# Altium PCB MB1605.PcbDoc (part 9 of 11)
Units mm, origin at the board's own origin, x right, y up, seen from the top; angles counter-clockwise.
Board outline 100 x 79.6 mm, 6 copper layers (Top Layer, Signal Layer 1, Signal Layer 2, Signal Layer 3, Signal Layer 4, Bottom Layer), stack 1.549 mm thick; 644 components, 529 nets, 2853 pads, 1462 vias.
Unrouted connection lines stored in the file: 2.
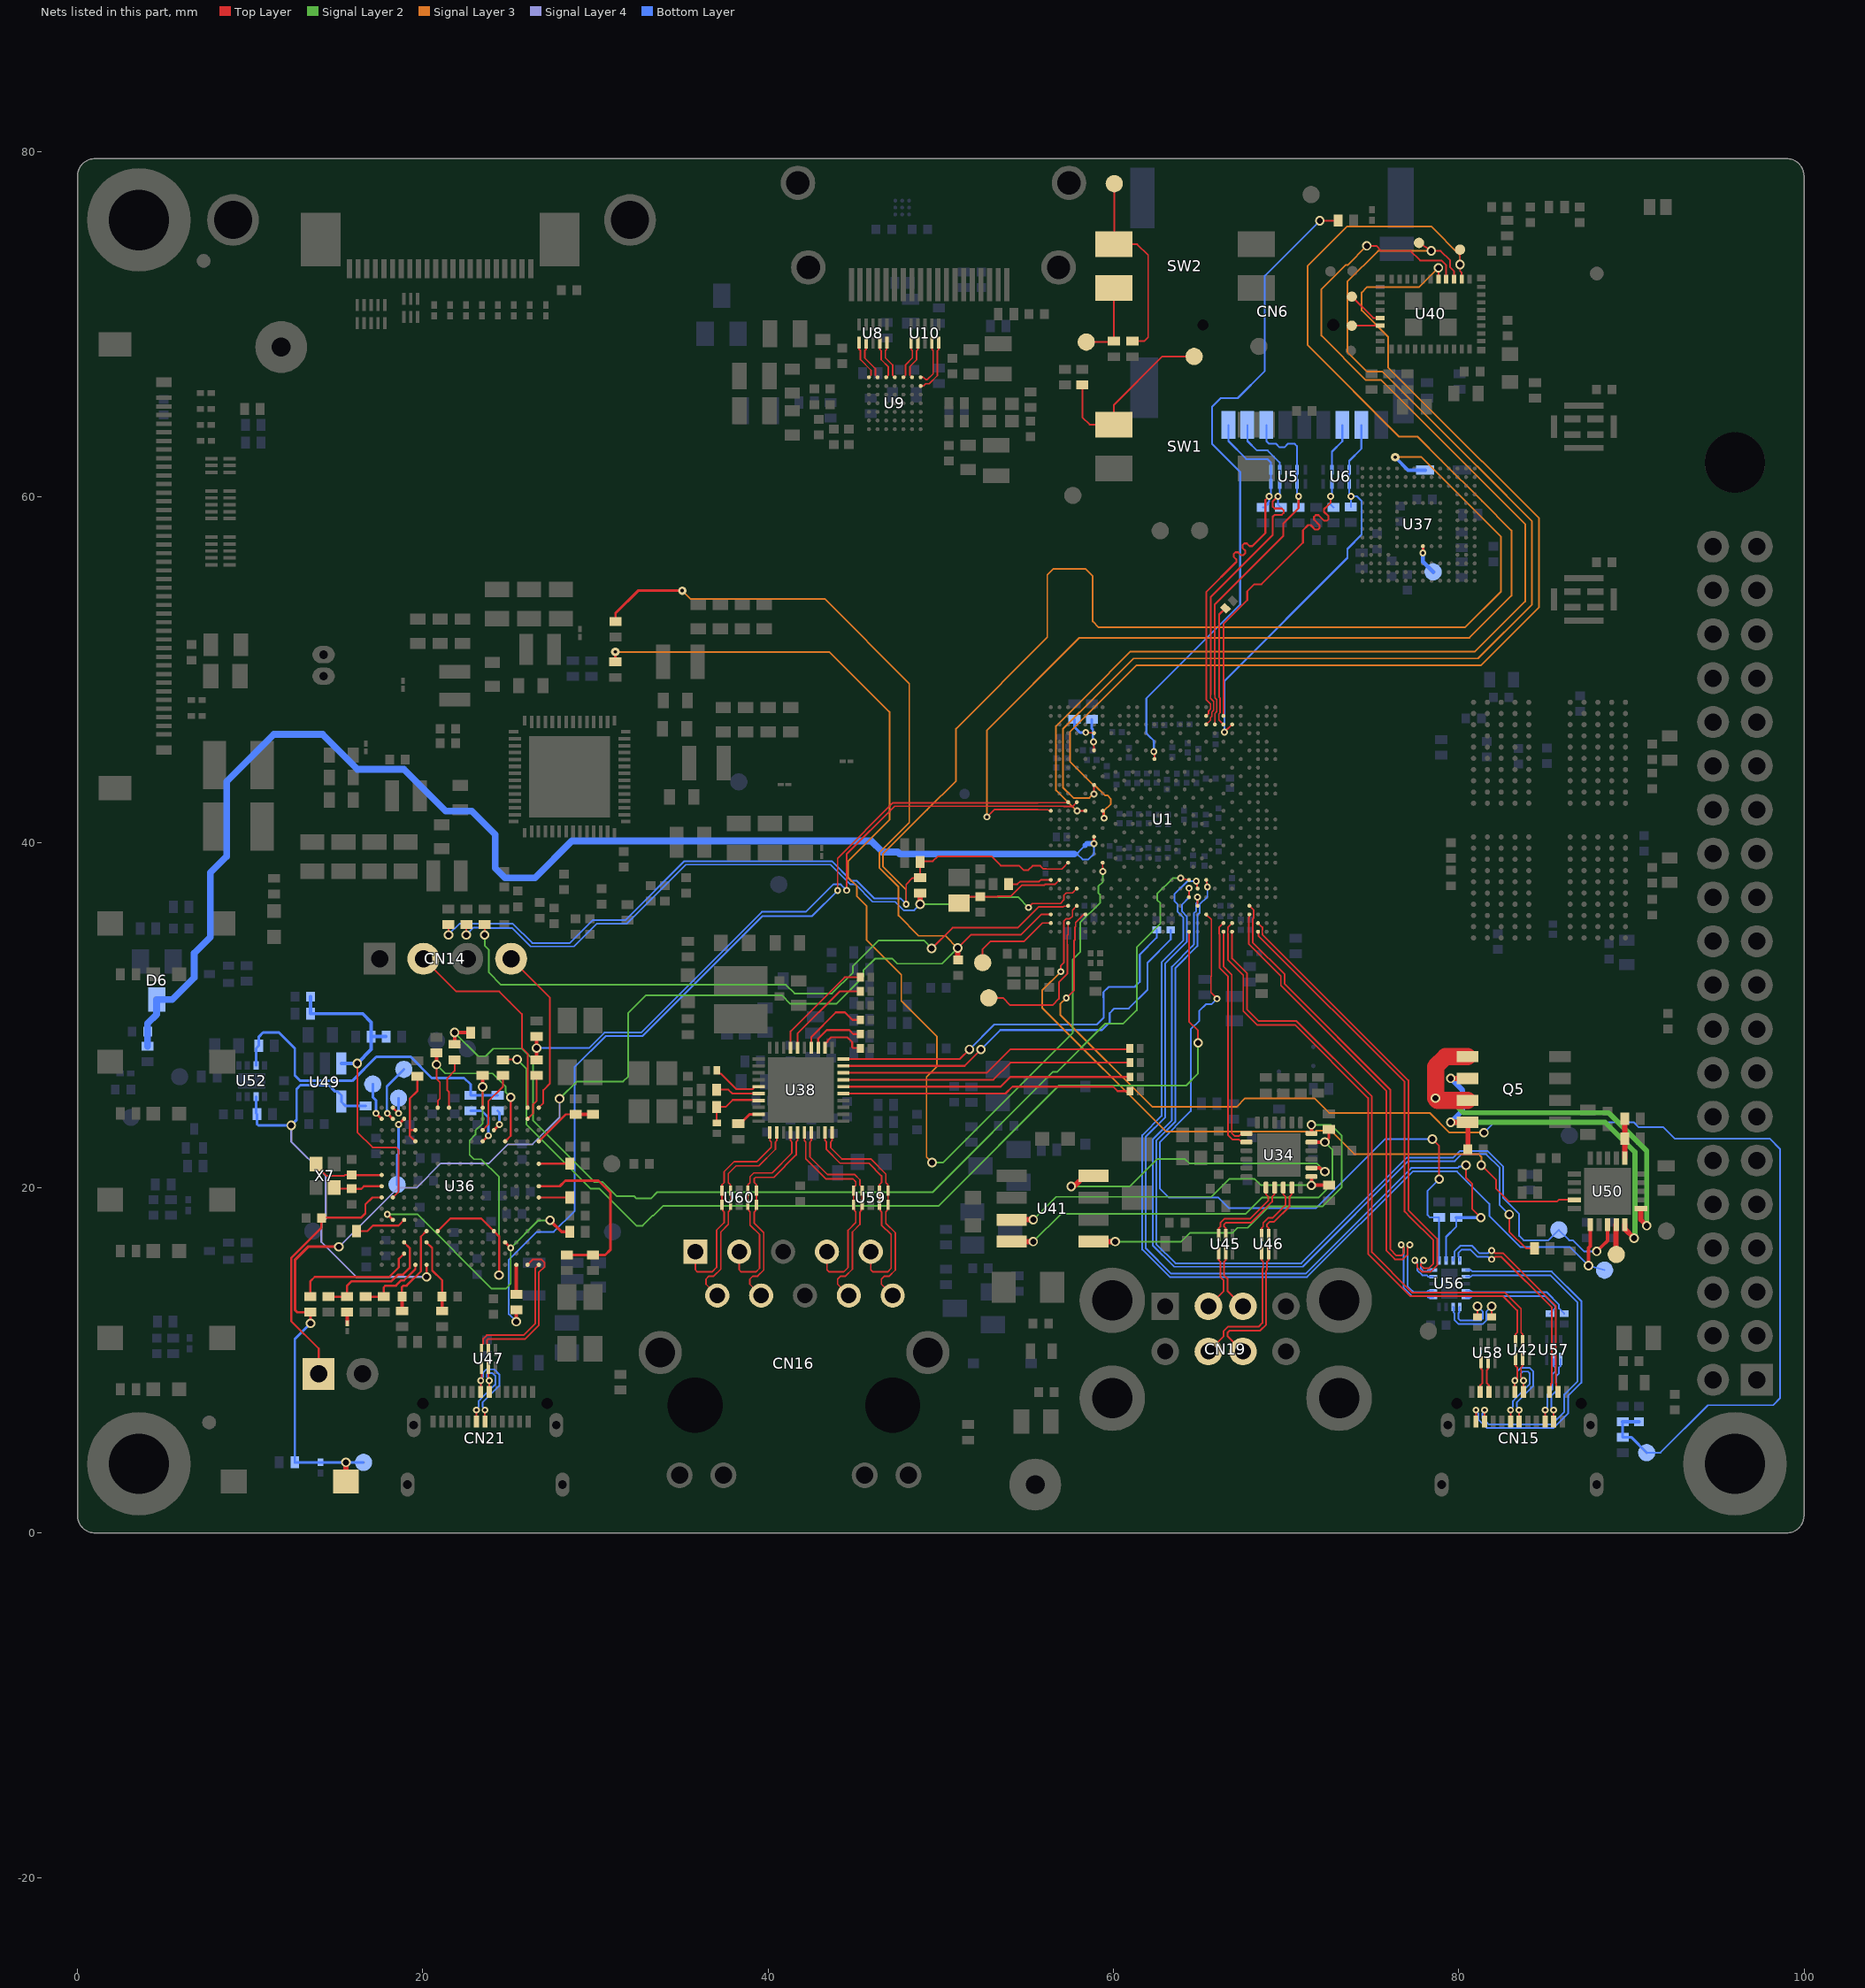
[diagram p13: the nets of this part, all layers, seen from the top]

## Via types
v1: diameter 0.55, hole 0.35, Top Layer to Bottom Layer, 823 vias
v2: diameter 0.4, hole 0.2, Top Layer to Bottom Layer, 235 vias
v3: diameter 0.4, hole 0.2, Top Layer to Bottom Layer, tented both sides, 216 vias
v4: diameter 0.5, hole 0.2, Top Layer to Bottom Layer, 159 vias
v5: diameter 0.25/0.3 (per signal layer), hole 0.1, Top Layer to Signal Layer 1, tented both sides, 29 vias

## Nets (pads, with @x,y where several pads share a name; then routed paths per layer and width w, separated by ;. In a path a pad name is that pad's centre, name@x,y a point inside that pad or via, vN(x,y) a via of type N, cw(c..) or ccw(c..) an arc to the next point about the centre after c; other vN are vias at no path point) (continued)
NetR121_2: R121.2 U38.24 | length 4.2
  Top Layer w0.11: U38.24@42.5,28.1 42.5,28.725 43.925,30.15 44.45,30.15 44.88,29.72 R121.2@45.345,29.72
NetR122_1: R122.1 SW1.3 TP24.1 | length 10.8
  Top Layer w0.1: R122.1@58.2,66.5 58.2,64.618 58.623,64.195 SW1.3@60.025,64.195 60.025,65.335 62.833,68.143 TP24.1@64.675,68.143
NetR123_1: R123.1 SW2.3 TP44.1 | length 11.5
  Top Layer w0.1: TP44.1@60.05,78.15 60.05,74.67 SW2.3@60.025,74.645 61.38,74.645 62.01,74.015 62.01,69.259 61.776,69.025 R123.1@61.1,69.025
NetR124_1: R124.1 SW2.4 TP31.1 | length 4.7
  Top Layer w0.1: TP31.1@58.425,68.975 59.975,68.975 R124.1@60.025,69.025 SW2.4@60.025,72.105
NetR147_2: R147.2 U38.23 | length 3.3
  Top Layer w0.11: U38.23@42.9,28.1 42.9,28.625 43.4,29.125 44.7,29.125 44.927,28.898 R147.2@45.345,28.898
NetR148_2: R148.2 U38.22 | length 2.9
  Top Layer w0.11: U38.22@43.3,28.1 43.3,28.35 43.345,28.395 43.381,28.395 43.445,28.459 43.445,28.514 43.636,28.705 44.147,28.705 44.595,28.705 44.868,28.432 44.868,28.146 44.933,28.082 45.327,28.082 R148.2@45.344,28.065
NetR149_2: R149.2 U38.27 | length 6.3
  Top Layer w0.11: U38.27@41.3,28.1 41.3,29.05 44.435,32.185 R149.2@45.345,32.185
NetR150_2: R150.2 U38.26 | length 5.5
  Top Layer w0.11: U38.26@41.7,28.1 41.7,28.925 44.14,31.365 R150.2@45.345,31.365
NetR155_2: R155.2 U36.B14 | length 2.7
  Top Layer w0.1: U36.B14@26.065,23.982 26.39,24.307 26.39,24.832 26.59,25.032 R155.2@26.59,26.507
NetR156_1: R156.1 U36.C4 U36.D4 | length 4.4
  Top Layer w0.12: U36.D4@19.565,22.682 19.24,23.007 19.24,23.332 ; U36.C4@19.565,23.332 19.24,23.332 ; R156.1@19.69,26.457 19.69,25.607 19.24,25.157 19.24,23.332
NetR161_2: R161.2 U38.20 | length 23.3
  Top Layer w0.11: U38.20@44.35,27.45 51.099,27.45 v1(51.656,28.007)
  Bottom Layer w0.11: v1(51.656,28.007) 53.099,29.449 59.037,29.449 59.434,29.846 59.434,31.012 59.426,31.02 59.426,31.326 59.723,31.623 61.229,31.623 61.525,31.919 61.525,33.498 62.506,34.479 R161.2@62.506,34.925
NetR164_2: R164.2 U38.19 | length 23.8
  Top Layer w0.11: U38.19@44.35,27.05 51.374,27.05 v1(52.322,27.998)
  Bottom Layer w0.11: v1(52.322,27.998) 53.449,29.125 59.331,29.125 59.784,29.578 59.784,30.104 60.055,30.375 60.888,30.375 61.981,31.469 61.981,33.039 63.319,34.377 R164.2@63.319,34.925
NetR167_2: R167.2 U38.18 | length 17.2
  Top Layer w0.11: U38.18@44.35,26.65 46.627,26.65 52.666,26.65 54.023,28.007 60.887,28.007 R167.2@60.945,28.065
NetR173_2: R173.2 U38.17 | length 17
  Top Layer w0.11: U38.17@44.35,26.25 53.044,26.25 54.034,27.24 R173.2@60.96,27.24
NetR176_2: R176.2 U38.35 | length 3
  Top Layer w0.11: R176.2@37.025,26.8 37.025,26.75 37.17,26.605 37.256,26.605 38.156,25.705 39.091,25.705 39.155,25.769 39.155,25.805 39.2,25.85 U38.35@39.45,25.85
NetR178_2: R178.2 U38.16 | length 16.8
  Top Layer w0.11: U38.16@44.35,25.85 53.462,25.85 54.027,26.415 R178.2@60.96,26.415
NetR181_1: R181.1 U36.F15 | length 1.8
  Top Layer w0.12: U36.F15@26.715,21.382 R181.1@28.515,21.382
NetR182_2: R182.2 U38.36 | length 2.5
  Top Layer w0.11: R182.2@37.025,25.675 37.7,25.675 37.925,25.45 U38.36@39.45,25.45
NetR185_2: R185.2 U38.15 | length 16.9
  Top Layer w0.11: U38.15@44.35,25.45 53.752,25.45 54.149,25.847 59.983,25.847 60.24,25.59 R185.2@60.96,25.59
NetR188_2: R188.2 R196.2 U38.37 | length 4.5
  Top Layer w0.11: U38.37@39.45,25.05 39.45,25.08 37.955,25.08 37.55,24.675 R188.2@37.025,24.675 ; R188.2@37.025,24.675 R196.2@37.025,23.75 R188.2@37.025,24.675
NetR194_1: R194.1 U36.J15 | length 1.8
  Top Layer w0.12: U36.J15@26.715,19.432 R194.1@28.515,19.432
NetR199_1: R199.1 U38.39 | length 1.4
  Top Layer w0.15: R199.1@38.275,23.7 38.37,23.7 38.92,24.25 U38.39@39.45,24.25
NetR211_2: R211.2 U36.R13 | length 1.7
  Top Layer w0.2: R211.2@25.415,13.812 U36.R13@25.415,15.532
NetR212_1: R212.1 U36.P3 | length 7.3
  Top Layer w0.12: R212.1@13.49,13.682 13.49,14.582 13.74,14.832 18.05,14.832 18.615,15.397 18.615,15.882 U36.P3@18.915,16.182
NetR231_1: R231.1 R232.2 U50.11 | length 2.3
  Top Layer w0.3: U50.11@89.613,21.723 89.613,22.848 R232.2@89.613,24.003
NetR240_1: R240.1 R241.1 R242.1 U52.7 | length 19.6
  Bottom Layer w0.15: U52.7@10.336,27.077 10.336,28.067 R242.1@10.486,28.217 10.486,28.723 10.745,28.982 11.665,28.982 12.586,28.061 12.586,26.503 12.904,26.186 15.912,26.186 17.302,27.575 19.3,27.575 20.521,26.354 22.393,26.354 22.765,25.982 R241.1@22.765,25.35 R240.1@24.335,25.35
NetR250_1: R250.1 U1.D6 | length 1.7
  Top Layer w0.1: v3(58.396,46.369) U1.D6@58.875,46.325
  Bottom Layer w0.15: R250.1@57.744,47.12 57.744,46.681 58.055,46.369 v3(58.396,46.369)
NetR251_1: R251.1 U1.F6 | length 1.8
  Top Layer w0.1: v3(58.85,45.825) U1.F6@58.875,45.325
  Bottom Layer w0.15: R251.1@58.751,47.12 58.751,46.59 58.81,46.531 58.81,45.865 v3(58.85,45.825)
NetTP12_1: TP12.1 U1.AF1 | length 5.4
  Top Layer w0.09: 55.625,35.07 55.645,35.09 55.652,35.09 55.887,35.325 U1.AF1@56.375,35.325
  Top Layer w0.1: TP12.1@52.427,33.031 52.427,33.809 52.875,34.258 54.813,34.258 55.625,35.07
NetTP14_1: TP14.1 U40.18 | length 1.6
  Top Layer w0.1: TP14.1@73.81,69.925 U40.18@75.45,69.925
NetTP20_1: TP20.1 U40.17 | length 2.2
  Top Layer w0.1: TP20.1@73.81,71.607 75.042,70.375 U40.17@75.45,70.375
NetTP21_1: TP21.1 U37.H5 | length 1.7
  Top Layer w0.15: v2(77.925,56.755) U37.H5@77.925,57.155
  Bottom Layer w0.25: v2(77.925,56.755) 77.925,56.256 TP21.1@78.516,55.665
NetTP26_1: TP26.1 U36.B2 | length 3.4
  Top Layer w0.15: v3(17.94,24.307) U36.B2@18.265,23.982
  Bottom Layer w0.15: v3(17.94,24.307) 17.915,24.332 17.915,25.865 TP26.1@18.9,26.85
NetTP27_1: TP27.1 U36.B3 | length 4
  Top Layer w0.15: v3(18.59,23.657) U36.B3@18.915,23.982
  Bottom Layer w0.15: TP27.1@18.505,20.182 18.505,21.877 18.59,21.962 v3(18.59,23.657)
NetTP28_1: TP28.1 U36.B1 | length 2.2
  Top Layer w0.15: v3(17.29,24.307) U36.B1@17.615,23.982
  Bottom Layer w0.15: TP28.1@17.098,26 17.098,25.25 17.29,25.057 v3(17.29,24.307)
NetTP29_1: TP29.1 U36.A2 | length 1.3
  Top Layer w0.15: U36.A2@18.265,24.632 v3(18.59,24.307)
  Bottom Layer w0.15: v3(18.59,24.307) TP29.1@18.59,25.182
NetTP38_1: TP38.1 U50.4 | length 1.7
  Top Layer w0.3: TP38.1@89.113,16.144 U50.4@89.113,17.873
NJTRST: TP42.1 U1.AF3 | length 9
  Top Layer w0.09: 57.325,34.075 57.325,34.605 57.375,34.655 U1.AF3@57.375,35.325
  Top Layer w0.1: TP42.1@52.78,30.993 53.598,30.993 54.023,30.568 56.469,30.568 56.837,30.936 56.837,31.895 57.325,32.383 57.325,34.075
NRST: B1.1 C33.2 R33.1 R81.1 R212.2 TP22.1 U1.AE1 U15.1 | length 113.5
  Top Layer w0.09: 55.625,35.636 55.814,35.825 U1.AE1@56.375,35.825
  Top Layer w0.1: C33.2@50.975,33.225 C33.2@51,33.2 ; v1(50.975,33.875) 51.758,34.658 54.647,34.658 55.625,35.636
  Top Layer w0.15: v1(13.49,12.137) R212.2@13.49,12.782 12.723,12.782 12.609,12.896 12.609,15.828 13.356,16.575 v1(15.137,16.575) ; R81.1@31.163,52.798 31.163,53.273 32.465,54.575 v4(35.025,54.575)
  Top Layer w0.3: B1.1@15.549,2.979 v1(15.549,4.09) ; C33.2@50.975,33.225 v1(50.975,33.875)
  Signal Layer 2 w0.1: v1(27.92,25.15) 28.92,26.15 31.601,26.15 31.9,26.449 31.9,30.121 32.924,31.145 40.789,31.145 41.284,30.65 43.949,30.65 45.514,32.216 45.514,32.586 46.19,33.261 47.201,33.261 47.49,32.972 50.072,32.972 v1(50.975,33.875)
  Signal Layer 3 w0.1: v4(35.025,54.575) 35.502,54.098 43.277,54.098 48.175,49.2 48.175,41.14 46.442,39.407 46.442,38.529 47.554,37.417 47.554,35.752 48.721,34.586 50.264,34.586 v1(50.975,33.875)
  Signal Layer 4 w0.1: v1(15.137,16.575) 18.553,19.991 19.629,19.991 21.045,21.407 23.829,21.407 24.929,22.507 26.353,22.507 27.92,24.074 v1(27.92,25.15)
  Bottom Layer w0.15: v1(13.49,12.137) 12.586,11.233 R33.1@12.586,4.09 U15.1@14.062,4.09 v1(15.549,4.09) TP22.1@16.565,4.09
NRSTC1MS: D7.2 R27.1 R59.1 R272.1 U1.W3 | length 110.3
  Top Layer w0.09: 56.11,38.46 57.01,38.46 U1.W3@57.375,38.825
  Top Layer w0.1: R59.1@21.48,35.245 21.488,35.237 v1(21.488,34.633) ; v2(47.997,36.42) 47.997,37.566 48.363,37.932 48.782,37.932 R272.1@48.805,37.955 R27.1@48.805,38.872 48.805,38.904 49.542,38.904 49.831,39.194 49.936,39.194 49.938,39.192 50.559,39.192 50.561,39.194 52.93,39.194 53.474,38.65 54.531,38.65 54.787,38.394 55.077,38.394 55.319,38.635 55.764,38.635 55.939,38.46 56.11,38.46
  Signal Layer 3 w0.1: v2(47.997,36.42) 47.997,37.257 46.642,38.611 46.642,39.324 49.196,41.878 49.204,41.878 50.883,43.557 50.883,46.589 56.169,51.875 56.169,55.485 56.534,55.85 58.361,55.85 58.797,55.414 58.797,52.793 59.141,52.45 80.367,52.45 82.45,54.533 82.45,57.701 77.84,62.311 v4(76.32,62.311)
  Bottom Layer w0.1: v1(21.488,34.633) 21.488,34.653 22.123,35.288 25.217,35.288 26.335,34.17 28.515,34.17 29.833,35.488 31.724,35.488 35.146,38.91 43.695,38.91 44.83,37.775 45.122,37.775 46.138,36.759 47.658,36.759 v2(47.997,36.42)
  Bottom Layer w0.2: v4(76.32,62.311) 77.068,61.563 D7.2@78.055,61.563
OSC32_IN: C86.1 U1.AA2 X1.2 | length 6.4
  Top Layer w0.09: 55.625,37.525 56,37.525 56.05,37.575 56.625,37.575 U1.AA2@56.875,37.825
  Top Layer w0.1: X1.2@51.059,36.475 51.434,36.85 53.271,36.85 53.296,36.875 54.052,36.875 54.702,37.525 55.625,37.525
OSC32_OUT: R64.1 U1.AA1 | length 2.5
  Top Layer w0.09: 56.05,37.825 U1.AA1@56.375,37.825
  Top Layer w0.1: R64.1@53.935,37.575 54.436,37.575 54.597,37.735 55.695,37.735 55.784,37.825 56.05,37.825
PMIC_WAKEUPn: R46.1 U1.W7 | length 69.4
  Top Layer w0.09: U1.W7@59.375,38.825 v3(59.387,38.317)
  Top Layer w0.15: R46.1@31.15,50.448 v4(31.15,51.033)
  Signal Layer 2 w0.1: v1(49.5,21.45) 50.111,21.45 57.646,28.985 57.646,33.218 58.075,33.647 58.075,35.343 59.225,36.493 59.225,36.97 59.119,37.076 59.119,37.455 59.387,37.722 v3(59.387,38.317)
  Signal Layer 3 w0.1: v4(31.15,51.033) 43.548,51.033 47.028,47.553 47.028,41.303 44.625,38.9 44.625,37.98 45.132,37.473 45.132,36.893 45.698,36.327 45.698,34.356 47.715,32.34 47.715,30.826 49.774,28.767 49.774,27.012 49.175,26.413 49.175,21.775 v1(49.5,21.45)
PWR_CPU_ON: R60.1 R272.2 U1.AB4 | length 41.5
  Top Layer w0.09: 55.625,36.455 56.215,36.455 56.22,36.46 56.93,36.46 57.125,36.655 57.125,36.929 57.271,37.075 57.625,37.075 U1.AB4@57.875,37.325
  Top Layer w0.095: 55.57,36.455 55.625,36.455
  Top Layer w0.1: v1(22.514,34.64) 22.514,35.229 R60.1@22.53,35.245 ; v2(55.077,36.225) 55.307,36.455 55.57,36.455
  Top Layer w0.3: v1@48.805,36.419 R272.2@48.805,37.055
  Signal Layer 2 w0.1: v1(48.806,36.417) 51.182,36.417 51.598,36.834 54.469,36.834 v2(55.077,36.225)
  Bottom Layer w0.1: v1(22.514,34.64) 22.944,35.07 23.756,35.07 23.781,35.045 25.177,35.045 26.252,33.97 28.742,33.97 30.06,35.288 31.807,35.288 35.229,38.71 43.612,38.71 44.747,37.575 45.039,37.575 46.055,36.559 47.363,36.559 47.852,36.07 48.459,36.07 v1(48.806,36.417)
PWR_ON: R61.1 U1.AD3 | length 39.6
  Top Layer w0.09: 56.084,36.26 57.09,36.26 57.128,36.298 57.348,36.298 U1.AD3@57.375,36.325
  Top Layer w0.1: v1(23.58,34.64) R61.1@23.58,35.245 ; v1(49.475,33.855) 50.678,35.058 54.455,35.058 55.657,36.26 56.084,36.26
  Signal Layer 2 w0.1: v1(23.58,34.64) 23.58,34.015 23.824,33.771 23.824,32.458 24.537,31.745 41.037,31.745 41.532,31.25 43.7,31.25 44.914,32.464 44.914,32.834 46.397,34.317 49.013,34.317 v1(49.475,33.855)
RJ452_D1_N: CN16.2 U38.2 U60.4 U60.7 | length 12.5
  Top Layer w0.09: CN16.2@37.055,13.75 36.4,14.405 36.4,14.695 36.577,14.872 36.856,14.872 37.26,15.276 37.26,17.432 37.7,17.872 37.7,18.597 37.77,18.667 37.77,18.957 U60.7@37.825,19.012 U60.4@37.825,19.832 37.825,20.167 37.7,20.292 37.7,20.815 38.145,21.26 39.46,21.26 40.425,22.225 40.425,22.65 40.5,22.725 U38.2@40.5,23.2
RJ452_D1_P: CN16.1 U38.1 U60.5 U60.6 | length 12.5
  Top Layer w0.09: CN16.1@35.785,16.29 35.785,15.245 35.908,15.122 36.752,15.122 37.01,15.38 37.01,17.536 37.45,17.976 37.45,18.597 37.38,18.667 37.38,18.957 U60.6@37.325,19.012 U60.5@37.325,19.832 37.325,20.167 37.45,20.292 37.45,20.919 38.041,21.51 39.356,21.51 40.175,22.329 40.175,22.65 40.1,22.725 U38.1@40.1,23.2
RJ452_D2_N: CN16.4 U38.5 U60.1 U60.10 | length 12.2
  Top Layer w0.09: CN16.4@39.595,13.75 38.94,14.405 38.94,14.695 39.117,14.872 39.396,14.872 39.75,15.226 39.75,17.389 39.2,17.939 39.2,18.597 39.27,18.667 39.27,18.957 U60.10@39.325,19.012 U60.1@39.325,19.832 39.325,20.167 39.2,20.292 39.2,20.529 39.27,20.599 40.329,20.599 41.625,21.895 41.625,22.65 41.7,22.725 U38.5@41.7,23.2
RJ452_D2_P: CN16.3 U38.4 U60.2 U60.9 | length 12.2
  Top Layer w0.09: CN16.3@38.325,16.29 38.325,15.245 38.448,15.122 39.292,15.122 39.5,15.33 39.5,17.285 38.95,17.835 38.95,18.597 38.88,18.667 38.88,18.957 U60.9@38.825,19.012 U60.2@38.825,19.832 38.825,20.167 38.95,20.292 38.95,20.632 39.166,20.849 40.225,20.849 41.375,21.999 41.375,22.65 41.3,22.725 U38.4@41.3,23.2
RJ452_D3_N: CN16.8 U38.7 U59.4 U59.7 | length 12.7
  Top Layer w0.09: U38.7@42.5,23.2 42.5,22.725 42.425,22.65 42.425,21.779 43.445,20.759 45.014,20.759 45.32,20.452 45.32,20.13 45.373,20.077 45.39,20.077 45.445,20.022 U59.7@45.445,19.012 45.39,18.957 45.39,18.667 45.32,18.597 45.32,17.872 44.88,17.432 44.88,15.276 44.476,14.872 44.197,14.872 44.02,14.695 44.02,14.405 CN16.8@44.675,13.75
RJ452_D3_P: CN16.7 U38.6 U59.5 U59.6 | length 12.7
  Top Layer w0.09: U38.6@42.1,23.2 42.1,22.725 42.175,22.65 42.175,21.675 43.341,20.509 44.91,20.509 45.07,20.349 45.07,20.13 45.017,20.077 45,20.077 44.945,20.022 U59.6@44.945,19.012 45,18.957 45,18.667 45.07,18.597 45.07,17.976 44.63,17.536 44.63,15.38 44.372,15.122 43.528,15.122 43.405,15.245 CN16.7@43.405,16.29
RJ452_D4_N: CN16.10 U38.10 U59.1 U59.10 | length 12.9
  Top Layer w0.09: U38.10@43.7,23.2 43.7,22.725 43.625,22.65 43.625,22.307 44.269,21.663 45.942,21.663 46.82,20.785 46.82,20.292 46.945,20.167 U59.1@46.945,19.832 U59.10@46.945,19.012 46.89,18.957 46.89,18.667 46.82,18.597 46.82,17.939 47.37,17.389 47.37,15.226 47.016,14.872 46.737,14.872 46.56,14.695 46.56,14.405 CN16.10@47.215,13.75
RJ452_D4_P: CN16.9 U38.9 U59.2 U59.9 | length 12.9
  Top Layer w0.09: U38.9@43.3,23.2 43.3,22.725 43.375,22.65 43.375,22.204 44.165,21.413 45.838,21.413 46.57,20.681 46.57,20.292 46.445,20.167 U59.2@46.445,19.832 U59.9@46.445,19.012 46.5,18.957 46.5,18.667 46.57,18.597 46.57,17.835 47.12,17.285 47.12,15.33 46.912,15.122 46.068,15.122 45.945,15.245 CN16.9@45.945,16.29
RX1_N: CN15.B10 U56.11 | length 20.2
  Top Layer w0.1: CN15.B10@81.5,6.46 v2(81.5,7.12)
  Bottom Layer w0.1: U56.11@80.408,14.836 80.698,14.836 80.788,14.926 85.299,14.926 86.882,13.343 86.882,8.793 86.111,8.023 86.111,7.01 85.392,6.291 84.25,6.291 81.726,6.291 81.629,6.388 81.36,6.657 81.36,6.911 81.5,7.051 v2(81.5,7.12)
RX1_P: CN15.B11 U56.10 | length 21.3
  Top Layer w0.1: CN15.B11@81,6.46 v2(81,7.12)
  Bottom Layer w0.1: U56.10@80.408,15.236 80.698,15.236 80.788,15.146 85.39,15.146 87.102,13.434 87.102,8.702 86.331,7.931 86.331,6.919 85.483,6.071 81.634,6.071 81.14,6.565 81.14,6.911 81,7.051 v2(81,7.12)
RX2_N: CN15.A10 U56.9 | length 12.4
  Top Layer w0.1: v2(81.9,15.852) 81.969,15.852 82.109,15.992 82.471,15.992 85.396,13.067 85.396,13.005 85.396,10.581 85.396,8.684 85.35,8.638 85.35,8.26 CN15.A10@85.25,8.16
  Bottom Layer w0.1: U56.9@80.068,15.776 80.068,15.916 79.978,16.006 79.978,16.214 80.18,16.416 80.67,16.416 81.094,15.992 81.691,15.992 81.831,15.852 v2(81.9,15.852)
RX2_P: CN15.A11 U56.8 | length 13.2
  Top Layer w0.1: v2(81.9,16.352) 81.969,16.352 82.109,16.212 82.562,16.212 85.616,13.158 85.616,8.689 85.65,8.655 85.65,8.26 CN15.A11@85.75,8.16
  Bottom Layer w0.1: U56.8@79.668,15.776 79.668,15.916 79.758,16.006 79.758,16.305 80.089,16.636 80.761,16.636 81.185,16.212 81.691,16.212 81.831,16.352 v2(81.9,16.352)
SD.SDMMC1_CK: R9.1 U1.C21 | length 7
  Top Layer w0.09: 66.115,47.085 66.115,47.434 66.175,47.494 66.175,48.356 66.125,48.406 66.125,48.575 66.125,48.615
  Top Layer w0.11: 66.115,47.085 U1.C21@66.375,46.825 ; 66.125,48.615 66.125,53.197 R9.1@66.49,53.562
SD.SDMMC1_CMD: CN6.3 R37.1 U1.C20 U5.4 U5.7 | length 21.9
  Top Layer w0.09: U1.C20@65.875,46.825 65.875,47.462 65.985,47.572 65.985,48.267 65.875,48.377 65.875,48.575
  Top Layer w0.11: 65.875,48.575 65.875,53.79 69.841,57.756 69.841,58.466 70.725,59.35 v2(70.725,60.042)
  Bottom Layer w0.11: CN6.3@68.86,64.175 68.86,63.24 69.013,63.087 69.417,63.087 69.626,62.877 69.897,62.877 70.106,63.087 70.491,63.087 70.625,62.952 U5.4@70.625,61.582 U5.7@70.625,60.762 70.625,60.142 v2(70.725,60.042) R37.1@70.725,59.393
SD.SDMMC1_D0: CN6.7 R38.1 U1.B21 U6.2 U6.9 | length 22.7
  Top Layer w0.11: U1.B21@66.375,47.325 66.375,52.65 67.75,54.025 67.75,54.538 68.162,54.95 68.57,54.95 70.976,57.356 70.976,58.076 71.272,58.372 71.426,58.372 71.686,58.112 71.841,58.112 71.944,58.215 71.944,58.369 71.617,58.696 71.617,58.85 71.72,58.953 71.875,58.953 72.201,58.627 72.356,58.627 72.459,58.73 72.459,58.884 72.199,59.144 72.199,59.299 72.406,59.506 72.577,59.677 v2(72.577,60.042)
  Bottom Layer w0.11: R38.1@72.75,59.393 72.577,59.566 v2(72.577,60.042) 72.654,60.12 U6.9@72.654,60.762 U6.2@72.654,61.582 72.654,62.629 73.26,63.235 CN6.7@73.26,64.175
SD.SDMMC1_D1: CN6.8 R39.1 U1.C22 U6.4 U6.7 | length 23.1
  Top Layer w0.11: v3(66.43,46.389) U1.C22@66.875,46.825
  Bottom Layer w0.11: v3(66.43,46.389) 66.43,49.352 73.554,56.476 73.554,56.996 74.375,57.816 74.375,59.775 74.108,60.042 v2(73.754,60.042) ; R39.1@73.754,59.43 v2(73.754,60.042) ; CN6.8@74.36,64.175 74.36,62.8 73.654,62.094 U6.4@73.654,61.582 U6.7@73.654,60.762 73.654,60.142 v2(73.754,60.042)
SD.SDMMC1_D2: CN6.1 R35.1 U1.B19 U5.1 U5.10 | length 22.4
  Top Layer w0.09: U1.B19@65.375,47.325 65.515,47.465 65.515,47.611 65.625,47.721 65.625,48.015 65.375,48.265
  Top Layer w0.11: 65.375,48.265 65.375,54.493 67.076,56.194 67.115,56.233 67.115,56.388 66.961,56.541 66.961,56.695 67.064,56.798 67.218,56.798 67.377,56.639 67.532,56.639 67.635,56.742 67.635,56.897 67.476,57.056 67.476,57.21 67.579,57.313 67.733,57.313 67.887,57.16 68.041,57.16 68.179,57.298 68.8,57.918 68.8,59.761 68.8,59.826 v2(69.016,60.042)
  Bottom Layer w0.11: CN6.1@66.66,64.175 66.66,63.24 67.698,62.202 68.919,62.202 69.125,61.996 U5.1@69.125,61.582 U5.10@69.125,60.762 69.125,60.151 v2(69.016,60.042) v2(69.016,60.042) 69.015,59.747 68.956,59.688 68.956,59.593 68.756,59.393 R35.1@68.661,59.393
SD.SDMMC1_D3: CN6.2 R36.1 U1.C19 U5.2 U5.9 | length 22.1
  Top Layer w0.09: U1.C19@65.375,46.825 65.625,47.075 65.625,47.229 65.695,47.299 65.695,47.537 65.805,47.647 65.805,48.166 65.63,48.342 65.63,48.575
  Top Layer w0.11: 65.63,48.575 65.63,54.198 69.225,57.793 69.225,58.443 69.225,58.862 69.334,58.972 69.752,58.972 69.861,59.081 69.861,59.226 69.752,59.336 69.334,59.336 69.225,59.445 69.225,59.742 69.504,60.021 v2(69.525,60.042)
  Bottom Layer w0.11: CN6.2@67.76,64.175 67.76,63.247 68.308,62.698 68.929,62.698 69.625,62.002 U5.2@69.625,61.582 U5.9@69.625,60.762 69.625,60.142 v2(69.525,60.042) 69.525,59.568 R36.1@69.7,59.393
SD.uSD_DETECT: R40.1 U1.G13 | length 38.6
  Top Layer w0.1: U1.G13@62.375,44.825 v3@62.375,45.3
  Top Layer w0.11: v1(71.95,76) 72.99,76 R40.1@73.015,76.025
  Bottom Layer w0.11: v3@62.343,45.253 62.343,45.88 62.045,46.178 61.906,46.317 61.906,48.34 67.341,53.775 67.341,61.453 65.707,63.087 65.707,65.218 66.215,65.726 67.197,65.726 68.768,67.297 68.768,72.818 v1(71.95,76)
  other v3: 62.34,45.25
SRC_GDPG: C94.1 Q5.2 Q5.4 R325.2 U50.5 | length 24.1
  Top Layer w0.2: Q5.2@80.528,26.329 Q5.2@80.533,26.334
  Top Layer w0.3: v1(79.533,23.789) Q5.4@80.528,23.789 ; v1(79.533,26.329) Q5.2@80.528,26.329 ; C94.1@80.533,22.224 Q5.4@80.533,23.794 ; U50.5@89.613,17.873 89.613,17.623 v1(90.163,17.073)
  Signal Layer 2 w0.3: v1(79.533,23.789) 88.476,23.789 90.2,22.065 90.2,17.11 v1(90.163,17.073)
  Bottom Layer w0.3: v1(79.533,23.789) 80.225,24.481 R325.2@80.225,25.178 80.225,25.637 v1(79.533,26.329)
SRC_GDPS: Q5.1 Q5.3 R325.1 U50.6 | length 25.5
  Top Layer w0.3: U50.6@90.538,18.798 90.538,18.148 v1(90.888,17.798)
  Top Layer w1: Q5.3@80.52,25.052 78.781,25.052 v1(78.655,25.178) 78.655,27.006 79.241,27.592 Q5.1@80.52,27.592
  Signal Layer 2 w0.3: v1(78.655,25.178) 79.433,25.178 80.273,24.338 88.683,24.338 90.888,22.133 v1(90.888,17.798)
  Bottom Layer w0.3: v1(78.655,25.178) R325.1@79.325,25.178
STLK_LED: R130.1 R131.2 U36.D15 | length 3.8
  Top Layer w0.12: U36.D15@26.715,22.682 28.283,24.25 R130.1@28.83,24.25
  Top Layer w0.2: R130.1@28.83,24.25 R131.2@29.858,24.25
STLK_NRST: C149.2 JP3.1 U36.J1 | length 14.7
  Top Layer w0.12: JP3.1@13.965,9.211 13.965,10.68 12.374,12.271 12.374,15.925 14.131,17.683 C149.2@14.131,18.239 ; C149.2@14.126,18.257 16.42,18.257 16.675,18.512 16.675,19.032 17.075,19.432 U36.J1@17.615,19.432
STLK_OSC_IN: C133.2 U36.G1 X7.1 | length 4.1
  Top Layer w0.1: X7.1@13.815,21.357 13.815,21.307 14.44,20.682 15.44,20.682 15.49,20.732 C133.2@15.885,20.732
  Top Layer w0.12: C133.2@15.885,20.732 U36.G1@17.615,20.732
STLK_OSC_OUT: C140.1 U36.H1 X7.3 | length 2.8
  Top Layer w0.1: X7.3@14.865,20.007 14.94,19.932 C140.1@15.885,19.932
  Top Layer w0.12: C140.1@15.885,19.932 16.44,19.932 16.59,20.082 U36.H1@17.615,20.082
STLK_SWCLK: CN14.2 U36.A14 | length 12.6
  Top Layer w0.1: CN14.2@20.035,33.257 21.93,31.363 24.431,31.363 25.045,30.748 25.74,30.053 25.74,28.092 26.065,27.767 U36.A14@26.065,24.632
STLK_SWDIO: CN14.4 U36.A15 | length 9.8
  Top Layer w0.1: CN14.4@25.115,33.257 27.365,31.007 27.365,26.04 26.975,25.65 26.975,24.892 U36.A15@26.715,24.632
STLK_UCPD_CC1_C: C157.1 R217.1 U36.M5 | length 5.3
  Top Layer w0.12: 19.058,14.325 19.89,15.157 19.89,17.157 U36.M5@20.215,17.482
  Top Layer w0.125: C157.1@18.795,13.682 18.795,14.251 18.868,14.325 19.058,14.325
  Top Layer w0.2: R217.1@18.795,12.857 C157.1@18.795,13.682
STLK_UCPD_CC2_C: C158.1 R218.1 U36.N5 | length 4.3
  Top Layer w0.12: U36.N5@20.215,16.832 20.54,16.507 20.54,15.207 21.115,14.632 C158.1@21.115,13.682
  Top Layer w0.2: R218.1@21.115,12.857 C158.1@21.115,13.682
STLK_USB_CN_N: CN21.A7 CN21.B7 U47.2 | length 5.5
  Top Layer w0.1: CN21.B7@23.1,6.46 v2(23.1,7.12) ; U47.2@23.8,9.561 23.8,8.87 v2(23.85,8.82) CN21.A7@23.85,8.16
  Bottom Layer w0.1: v2(23.1,7.12) 23.1,7.189 23.24,7.329 23.24,7.642 23.324,7.726 23.961,8.364 24.205,8.607 24.205,9.089 24.039,9.255 23.769,9.255 23.71,9.196 23.71,9.029 23.85,8.889 v2(23.85,8.82)
STLK_USB_CN_P: CN21.A6 CN21.B6 U47.1 | length 6.3
  Top Layer w0.1: CN21.A6@23.35,8.16 v2(23.35,8.82) 23.4,8.87 U47.1@23.4,9.561 ; CN21.B6@23.6,6.46 v2(23.6,7.12)
  Bottom Layer w0.1: v2(23.35,8.82) 23.35,8.889 23.49,9.029 23.49,9.288 23.677,9.475 24.13,9.475 24.425,9.18 24.425,8.516 23.46,7.551 23.46,7.329 23.6,7.189 v2(23.6,7.12)
STLK_USB_N: U36.R14 U47.5 | length 8.9
  Top Layer w0.1: U47.5@23.8,10.611 23.8,10.861 23.71,10.951 23.71,11.154 23.788,11.232 25.93,11.232 26.725,12.027 26.725,15.1 27.05,15.425 27.05,15.65 26.85,15.85 26.383,15.85 U36.R14@26.065,15.532
STLK_USB_P: U36.R15 U47.6 | length 7.5
  Top Layer w0.1: U47.6@23.4,10.611 23.4,10.861 23.49,10.951 23.49,11.245 23.697,11.452 25.839,11.452 26.505,12.118 26.505,15.322 U36.R15@26.715,15.532
STLK_VCP_RX: R154.1 U36.C10 | length 3.7
  Top Layer w0.1: U36.C10@23.465,23.332 23.79,23.657 23.79,24.994 24.64,25.844 R154.1@24.64,26.507
STLK_VCP_TX: R134.1 U36.A7 | length 3
  Top Layer w0.1: U36.A7@21.515,24.632 21.515,25.531 21.415,25.631 21.415,26.337 21.84,26.762 R134.1@21.84,27.407
T_JTDI: R207.1 U36.L3 | length 3
  Top Layer w0.12: R207.1@16.165,17.482 16.79,17.482 17.115,17.807 18.59,17.807 U36.L3@18.915,18.132
T_PWR_EN: R229.2 R239.2 U36.R5 U49.4 U52.2 | length 26
  Top Layer w0.12: v1(20.215,14.832) U36.R5@20.215,15.532
  Signal Layer 4 w0.12: v1(12.374,23.612) 12.374,22.673 14.374,20.673 14.374,18.214 14.126,17.966 14.126,16.853 16.147,14.832 v1(20.215,14.832)
  Bottom Layer w0.15: U52.2@10.336,25.277 10.336,24.307 R239.2@10.386,24.257 10.386,23.7 10.474,23.612 v1(12.374,23.612) 12.688,23.926 12.688,25.713 12.905,25.931 14.553,25.931 14.916,25.568 15.056,25.568 15.281,25.343 U49.4@15.281,24.993 15.281,24.969 15.506,24.744 R229.2@16.69,24.744
T_PWR_EXT: R215.1 R216.1 U36.R4 | length 4.1
  Top Layer w0.12: R215.1@16.69,13.682 R216.1@17.74,13.682 17.74,14.232 17.833,14.325 18.445,14.325 18.752,14.632 18.915,14.632 19.565,15.282 U36.R4@19.565,15.532
T_PWR_INT: C25.2 R226.2 R227.2 R230.2 U36.J2 U49.3 | length 18.9
  Top Layer w0.1: v1(16.202,27.193) 16.202,23.213 17.086,22.329 18.454,22.329 18.59,22.193 18.59,19.757 U36.J2@18.265,19.432
  Bottom Layer w0.2: C25.2@13.492,31.068 R230.2@13.492,30.075 16.52,30.075 17.015,29.58 R226.2@17.015,28.75 ; U49.3@15.281,27.193 v1(16.202,27.193) 17.015,28.005 R226.2@17.015,28.75 ; R227.2@17.865,28.75 R226.2@17.015,28.75
T_PWR_LED: R132.2 R133.2 U36.H15 | length 10.5
  Top Layer w0.15: U36.H15@26.715,20.082 27.935,20.082 28.26,20.407 30.181,20.407 30.858,19.73 30.858,16.389 30.563,16.094 R132.2@29.85,16.094 R133.2@28.35,16.094
T_PWR_SEL1: R241.2 U36.D10 | length 2.7
  Top Layer w0.15: U36.D10@23.465,22.682 v3(23.79,23.007)
  Bottom Layer w0.15: R241.2@22.765,24.45 23.41,24.45 23.79,24.07 v3(23.79,23.007)
T_PWR_SEL2: R240.2 U36.C11 | length 1.3
  Top Layer w0.15: U36.C11@24.115,23.332 v3(24.44,23.657)
  Bottom Layer w0.15: R240.2@24.335,24.45 24.44,24.345 v3(24.44,23.657)
T_SWCLK: R153.1 U36.A10 U36.M6 U36.M11 | length 20.6
  Top Layer w0.12: U36.M6@20.865,17.482 21.603,18.22 23.377,18.22 U36.M11@24.115,17.482 24.415,17.182 v1(24.415,14.932) ; U36.A10@23.465,24.632 v1(23.465,25.832)
  Top Layer w0.2: v1(23.465,25.832) R153.1@23.465,26.507
  Signal Layer 2 w0.1: v1(23.465,25.832) 23.465,23.715 23.05,23.3 23.05,23.072 22.705,22.727 22.705,21.902 22.96,21.647 23.378,21.647 24.415,20.61 v1(24.415,14.932)
T_SWDIO: R209.1 U36.L2 U36.N12 | length 16.4
  Top Layer w0.15: v3(17.94,18.457) U36.L2@18.265,18.132 ; U36.N12@24.765,16.832 v3(25.09,16.507)
  Top Layer w0.2: v1(27.37,18.107) 28.034,17.443 R209.1@28.515,17.443
  Signal Layer 2 w0.1: v3(17.94,18.457) 19.69,18.457 23.997,14.15 24.8,14.15 25.09,14.44 v3(25.09,16.507) 26.69,18.107 v1(27.37,18.107)
T_SWO: R129.1 U36.A6 U36.D12 | length 11.3
  Top Layer w0.1: v1(20.79,27.132) 20.79,26.303 20.99,26.103 20.99,25.157 20.865,25.032 U36.A6@20.865,24.632
  Top Layer w0.12: U36.D12@24.765,22.682 25.09,23.007 v1(25.09,25.232)
  Top Layer w0.2: v1(20.79,27.132) R129.1@20.79,27.807
  Signal Layer 2 w0.1: v1(20.79,27.132) 21.304,26.618 24.029,26.618 24.785,25.862 24.785,25.537 v1(25.09,25.232)
T_VCC: LNK13.2 R214.2 | length 0.6
  Top Layer w0.2: LNK13.2@15.615,12.137 R214.2@15.615,12.782
T_VCC_AIN: R213.1 R214.1 U36.N3 | length 7.4
  Top Layer w0.12: R213.1@14.54,13.682 R214.1@15.615,13.682 15.615,14.325 15.873,14.582 18.177,14.582 18.561,14.966 18.856,14.966 19.24,15.35 19.24,16.507 U36.N3@18.915,16.832
TCPP_EN: R10.1 U1.AD18 | length 51.2
  Top Layer w0.1: U1.AD18@64.875,36.325 v3(64.875,36.829) ; v1(82.926,18.448) 82.926,17.455 83.896,16.485 R10.1@84.4,16.485
  Bottom Layer w0.1: v3(64.875,36.829) 64.866,36.82 64.866,36.543 64.798,36.474 64.798,36.026 64.658,35.887 64.658,34.075 64.579,33.995 64.579,33.992 63.387,32.8 63.387,23.901 62.28,22.793 62.28,16.654 63.514,15.42 70.966,15.42 77.087,21.54 79.771,21.54 80.161,21.93 81.588,21.93 82.37,21.148 82.37,19.984 82.368,19.981 82.368,19.006 v1(82.926,18.448)
TCPP_INTN: U1.AD4 U50.19 | length 43
  Top Layer w0.09: 57.125,34.075 57.125,35.429 57.271,35.575 57.479,35.575 57.625,35.721 57.625,36.075 U1.AD4@57.875,36.325
  Top Layer w0.1: v2(56.956,32.51) 56.956,32.865 57.125,33.033 57.125,34.075 ; v1(81.307,21.305) 82.17,20.443 82.17,19.94 82.9,19.21 85.712,19.21 85.799,19.298 U50.19@86.688,19.298
  Signal Layer 3 w0.1: v2(56.956,32.51) 55.868,31.421 55.868,30.421 63.051,23.238 71.27,23.238 71.294,23.215 71.646,23.215 71.723,23.292 72.609,23.292 73.95,21.951 81.142,21.951 81.307,21.786 v1(81.307,21.305)
TMDS_CLK_N: U9.B7 U10.10 | length 3.2
  Top Layer w0.09: U9.B7@48.836,66.435 48.996,66.435 49.121,66.56 49.329,66.56 49.804,67.035 49.804,68.478 49.879,68.553 U10.10@49.879,68.948
TMDS_CLK_P: U9.A7 U10.9 | length 2.7
  Top Layer w0.09: U9.A7@48.836,66.935 48.996,66.935 49.121,66.81 49.226,66.81 49.554,67.139 49.554,67.211 49.554,68.15 49.554,68.478 49.479,68.553 U10.9@49.479,68.948
TMDS_D0_N: U9.A6 U10.7 | length 2.3
  Top Layer w0.09: U9.A6@48.336,66.935 48.211,67.06 48.211,67.567 48.604,67.96 48.604,68.478 48.679,68.553 U10.7@48.679,68.948
TMDS_D0_P: U9.A5 U10.6 | length 2.3
  Top Layer w0.09: U9.A5@47.836,66.935 47.961,67.06 47.961,67.67 48.354,68.063 48.354,68.478 48.279,68.553 U10.6@48.279,68.948
TMDS_D1_N: U8.10 U9.A4 | length 2.3
  Top Layer w0.09: U8.10@46.872,68.948 46.872,68.553 46.797,68.478 46.797,68.063 47.211,67.649 47.211,67.06 U9.A4@47.336,66.935
TMDS_D1_P: U8.9 U9.A3 | length 2.3
  Top Layer w0.09: U8.9@46.472,68.948 46.472,68.553 46.547,68.478 46.547,67.96 46.961,67.546 46.961,67.06 U9.A3@46.836,66.935
TMDS_D2_N: U8.7 U9.A2 | length 2.4
  Top Layer w0.09: U8.7@45.672,68.948 45.672,68.553 45.597,68.478 45.597,68.063 46.211,67.448 46.211,67.06 U9.A2@46.336,66.935
TMDS_D2_P: U8.6 U9.A1 | length 2.4
  Top Layer w0.09: U8.6@45.272,68.948 45.272,68.553 45.347,68.478 45.347,67.959 45.961,67.345 45.961,67.06 U9.A1@45.836,66.935
TX1_N: CN15.A3 U58.2 | length 1.8
  Top Layer w0.1: U58.2@81.7,9.888 81.7,9.493 81.625,9.418 81.625,9.144 81.625,8.68 81.75,8.555 CN15.A3@81.75,8.16
TX1_P: CN15.A2 U58.1 | length 1.8
  Top Layer w0.1: CN15.A2@81.25,8.16 81.25,8.555 81.375,8.68 81.375,9.144 81.375,9.419 81.3,9.493 U58.1@81.3,9.888
TX2_N: CN15.B3 U57.2 | length 3.9
  Top Layer w0.1: CN15.B3@85,6.46 v2(85,7.12)
  Bottom Layer w0.1: v2(85,7.12) 85.14,7.26 85.14,8.032 85.429,8.32 85.429,9.187 85.588,9.346 85.588,9.583 85.498,9.673 U57.2@85.498,10.073
TX2_P: CN15.B2 U57.1 | length 3.9
  Top Layer w0.1: CN15.B2@85.5,6.46 v2(85.5,7.12)
  Bottom Layer w0.1: v2(85.5,7.12) 85.36,7.26 85.36,7.941 85.649,8.229 85.649,9.096 85.808,9.255 85.808,9.583 85.898,9.673 U57.1@85.898,10.073
TX10_N: C265.1 U56.16 | length 4.4
  Top Layer w0.1: C265.1@81.906,12.516 v1(81.906,13.13)
  Bottom Layer w0.1: U56.16@79.668,13.096 79.699,13.065 79.699,12.775 79.758,12.716 79.758,12.331 79.992,12.096 81.383,12.096 81.606,12.32 81.606,12.831 v1(81.906,13.13)
TX10_P: C100.1 U56.15 | length 3.7
  Top Layer w0.1: C100.1@81.087,12.516 v1(81.087,13.13)
  Bottom Layer w0.1: U56.15@80.068,13.096 80.037,13.065 80.037,12.775 79.978,12.716 79.978,12.422 80.084,12.316 80.175,12.316 81.158,12.316 81.291,12.316 81.386,12.411 81.386,12.831 v1(81.087,13.13)
TX20_N: C267.1 U56.14 | length 6
  Bottom Layer w0.1: U56.14@80.408,13.636 80.698,13.636 80.788,13.726 82.375,13.726 83.7,13.726 84.995,13.726 85.592,13.13 85.592,13.001 C267.1@85.292,12.701
TX20_P: C266.1 U56.13 | length 6.4
  Bottom Layer w0.1: U56.13@80.408,14.036 80.698,14.036 80.788,13.946 85.087,13.946 85.812,13.221 85.812,13.001 C266.1@86.111,12.701
UART5_RX: R125.1 R155.1 U1.M4 | length 40.1
  Top Layer w0.09: 55.625,42.094 57.123,42.094 57.141,42.075 57.625,42.075 57.87,42.32 U1.M4@57.875,42.32
  Top Layer w0.093: 55.56,42.094 55.625,42.094
  Top Layer w0.1: v2(44.55,37.221) 44.55,39.322 47.321,42.094 55.56,42.094
  Top Layer w0.2: R155.1@26.59,27.407 v1(26.59,28.082) R125.1@26.59,28.757
  Bottom Layer w0.1: v1(26.59,28.082) 29.612,28.082 30.512,28.982 32.644,28.982 39.638,35.976 42.189,35.976 43.773,37.56 44.211,37.56 v2(44.55,37.221)
UART5_TX: R211.1 U1.M3 | length 53.8
  Top Layer w0.09: 55.625,42.294 57.252,42.294 57.257,42.298 57.348,42.298 U1.M3@57.375,42.325
  Top Layer w0.1: v2(44.025,37.21) 44.025,39.08 47.239,42.294 55.625,42.294
  Top Layer w0.2: v1(25.415,12.237) R211.1@25.415,12.912
  Bottom Layer w0.1: v1(25.415,12.237) 24.977,12.675 24.977,15.819 26.59,17.432 27.585,17.432 28.785,18.632 28.785,26.972 30.595,28.782 32.727,28.782 39.67,35.725 42.54,35.725 v2(44.025,37.21)
UCPD_CC1: TP37.1 U1.AB18 U50.1 | length 58.9
  Top Layer w0.1: v3(64.8,37.75) U1.AB18@64.875,37.325
  Top Layer w0.2: v1(87.515,15.488) 87.515,16.507 87.613,16.604 U50.1@87.613,17.873
  Bottom Layer w0.1: v3(64.8,37.75) 64.28,37.75 63.529,36.999 63.529,36.614 63.714,36.43 63.714,35.984 64.058,35.64 64.058,34.32 63.813,34.075 62.787,33.049 62.787,24.149 61.67,23.032 61.67,16.415 63.266,14.82 71.214,14.82 77.335,20.94 79.898,20.94 81.77,19.068 81.77,18.371 83.591,16.55 86.453,16.55 v1(87.515,15.488) TP37.1@88.449,15.218
UCPD_CC2: TP36.1 U1.AA19 U50.3 | length 57.5
  Top Layer w0.1: U1.AA19@65.375,37.825 v3(65.444,37.416)
  Top Layer w0.2: v1(87.99,16.31) 88.303,16.622 88.309,16.622 88.588,16.901 88.588,16.907 88.613,16.932 U50.3@88.613,17.873
  Bottom Layer w0.1: v3(65.444,37.416) 65.444,36.852 64.988,36.395 64.988,35.909 64.858,35.78 64.858,34.075 64.858,33.989 63.587,32.717 63.587,23.818 62.48,22.711 62.48,16.737 63.597,15.62 70.883,15.62 77.004,21.74 79.689,21.74 80.078,22.13 81.671,22.13 82.57,21.231 82.57,19.901 82.568,19.899 82.568,19.407 83.5,18.475 83.5,17.207 83.757,16.95 85.198,16.95 TP36.1@85.798,17.551 86.399,16.95 86.618,16.95 87.258,16.31 v1(87.99,16.31)
USART1_CTS: U1.N7 U40.5 | length 65
  Top Layer w0.1: U1.N7@59.375,41.825 59.437,41.504 v3(59.457,41.4) ; U40.5@78.825,72.625 v1(78.825,73.275)
  Signal Layer 3 w0.1: v3(59.457,41.4) 59.457,41.826 59.855,42.224 59.855,42.514 59.644,42.725 59.505,42.725 58.975,43.255 58.9,43.255 57.479,44.676 57.479,46.408 59.646,48.575 61.321,50.25 81.278,50.25 84.65,53.622 84.65,58.764 81.346,62.068 81.306,62.109 75.919,67.496 75.919,69.265 74.375,70.809 74.375,71.851 74.674,72.15 77.7,72.15 v1(78.825,73.275)
USART1_RTS: U1.N5 U40.4 | length 69.1
  Top Layer w0.09: v3(57.9,41.825) U1.N5@58.375,41.825
  Top Layer w0.1: v1(74.675,74.55) 75.225,74.55 75.5,74.275 77.191,74.275 77.766,73.7 79.001,73.7 79.275,73.426 U40.4@79.275,72.625
  Signal Layer 3 w0.1: v3(57.9,41.825) 57.863,41.825 56.679,43.009 56.679,46.739 58.515,48.575 60.99,51.05 80.947,51.05 83.85,53.953 83.85,58.433 81.346,60.937 80.174,62.109 75.508,66.775 74.613,66.775 72.045,69.343 72.045,72.041 73.443,73.44 73.565,73.44 v1(74.675,74.55)
USART1_RX: TP9.1 U1.K6 U40.3 | length 68.8
  Top Layer w0.09: v3(58.875,42.8) U1.K6@58.875,43.325
  Top Layer w0.1: TP9.1@77.7,74.725 v1(78.406,74.258) 78.957,74.258 79.506,73.708 79.506,73.306 79.725,73.087 U40.3@79.725,72.625
  Signal Layer 3 w0.1: v3(58.875,42.8) 58.84,42.8 58.61,42.57 57.686,42.57 57.079,43.178 57.079,46.573 59.08,48.575 61.155,50.65 81.113,50.65 84.25,53.787 84.25,58.599 81.346,61.502 80.74,62.109 75.574,67.275 74.679,67.275 73.55,68.404 73.55,72.475 75.333,74.258 v1(78.406,74.258)
USART1_TX: TP1.1 U1.N1 U40.2 | length 79.9
  Top Layer w0.09: 55.625,41.894 56.207,41.894 56.251,41.85 56.35,41.85 U1.N1@56.375,41.825
  Top Layer w0.1: v2(52.675,41.475) 53.094,41.894 55.625,41.894 ; TP1.1@80.075,74.331 v1(80.075,73.473) 80.075,73.1 80.175,73 U40.2@80.175,72.625
  Signal Layer 3 w0.1: v2(52.675,41.475) 52.675,46.498 58.027,51.85 80.616,51.85 83.05,54.284 83.05,58.059 81.346,59.763 79.001,62.109 77.609,63.5 76.55,63.5 71.245,68.805 71.245,73.371 73.549,75.675 78.4,75.675 80.075,74 v1(80.075,73.473)
USART2_RX: R107.1 R134.2 U1.AA17 | length 61.7
  Top Layer w0.1: v3(63.9,37.925) 63.94,37.885 64.055,37.885 U1.AA17@64.375,37.825
  Top Layer w0.2: R134.2@21.84,28.307 v1(21.84,28.982) R107.1@22.775,28.982
  Signal Layer 2 w0.1: v1(21.84,28.982) 23.206,27.616 23.641,27.616 24.077,28.052 25.736,28.052 26.387,27.401 26.387,23.879 29.929,20.337 30.398,20.337 31.235,19.5 32.251,19.5 32.376,19.375 33.212,19.375 33.575,19.737 49.53,19.737 56.505,26.712 56.751,26.712 59.539,29.5 60.576,29.5 61.35,30.274 61.35,33.93 62.725,35.305 62.725,36.47 62.525,36.67 62.525,37.007 63.443,37.925 v3(63.9,37.925)
USART2_TX: R154.2 U1.AG17 | length 58.2
  Top Layer w0.09: 64.375,34.075 U1.AG17@64.375,34.825
  Top Layer w0.1: R154.2@24.64,27.407 24.658,27.425 v1(25.457,27.425) ; 64.375,34.075 64.375,29.626 64.904,29.097 v1(64.904,28.387)
  Signal Layer 2 w0.1: v1(25.457,27.425) 25.987,26.895 25.987,23.666 29.716,19.937 30.233,19.937 32.37,17.8 32.726,17.8 33.295,18.369 33.339,18.369 33.908,18.937 49.861,18.937 56.836,25.912 64.208,25.912 64.904,26.608 v1(64.904,28.387)
USB1CN_N: CN19.T2 U45.1 | length 3.6
  Top Layer w0.1: CN19.T2@65.5,13.13 66.39,14.02 66.39,14.627 66.19,14.827 66.19,15.71 66.1,15.8 U45.1@66.1,16.2
USB1CN_P: CN19.T3 U45.2 | length 3.6
  Top Layer w0.1: U45.2@66.5,16.2 66.5,15.8 66.41,15.71 66.41,14.918 66.61,14.718 66.61,14.02 CN19.T3@67.5,13.13
USB2CN_N: CN19.B2 U46.1 | length 8.1
  Top Layer w0.1: CN19.B2@65.5,10.51 66.39,11.4 66.39,11.7 66.627,11.937 68.404,11.937 68.625,12.157 68.625,15.281 68.674,15.33 68.674,15.71 68.584,15.8 U46.1@68.584,16.2
USB2CN_P: CN19.B3 U46.2 | length 8.1
  Top Layer w0.1: CN19.B3@67.5,10.51 66.61,11.4 66.61,11.609 66.718,11.717 68.495,11.717 68.845,12.066 68.845,15.19 68.894,15.239 68.894,15.71 68.984,15.8 U46.2@68.984,16.2
USB3RX_N: U1.AF25 U56.4 | length 27.7
  Top Layer w0.09: 68.625,34.721 68.625,34.936
  Top Layer w0.1: U1.AF25@68.375,35.325 68.625,35.075 68.625,34.936 ; 68.625,34.721 68.625,34.669 77.08,26.214 77.08,18.706 78.75,17.036 78.75,15.5 78.366,15.116 77.871,15.116 77.598,15.39 77.598,15.584 77.458,15.724 v2(77.458,15.792)
  Bottom Layer w0.1: v2(77.458,15.792) 77.598,15.652 77.598,15.218 77.89,14.926 78.148,14.926 78.238,14.836 U56.4@78.528,14.836
USB3RX_P: U1.AG25 U56.5 | length 26
  Top Layer w0.1: U1.AG25@68.375,34.825 68.4,34.8 68.4,34.583 76.86,26.123 76.86,18.615 77.21,18.265 78.53,16.945 78.53,16.544 78.53,15.591 78.275,15.336 77.963,15.336 77.818,15.481 77.818,15.584 77.958,15.724 v2(77.958,15.792)
  Bottom Layer w0.1: v2(77.958,15.792) 77.818,15.652 77.818,15.309 77.981,15.146 78.148,15.146 78.238,15.236 U56.5@78.528,15.236
USB3TX_N: U1.AD24 U56.1 | length 29.3
  Top Layer w0.09: 68.125,35.62 68.125,35.936
  Top Layer w0.1: U1.AD24@67.875,36.325 68.125,36.075 68.125,35.936 ; 68.125,35.62 68.066,35.561 68.066,34.201 69.917,32.349 69.917,31.796 76.032,25.681 76.032,16.435 76.395,16.072 76.679,16.072 76.807,16.2 76.807,16.55 v2(76.667,16.69)
  Bottom Layer w0.1: v2(76.667,16.69) 76.807,16.55 76.807,14.204 77.286,13.726 78.148,13.726 78.238,13.636 U56.1@78.528,13.636
USB3TX_P: U1.AE24 U56.2 | length 29.1
  Top Layer w0.1: U1.AE24@67.875,35.825 67.859,35.809 67.859,35.666 67.846,35.652 67.846,34.11 69.697,32.258 69.697,31.705 75.812,25.59 75.812,16.344 76.304,15.852 76.771,15.852 77.027,16.109 77.027,16.55 v2(77.167,16.69)
  Bottom Layer w0.1: v2(77.167,16.69) 77.027,16.55 77.027,15.198 77.027,14.296 77.173,14.15 77.377,13.946 78.148,13.946 78.238,14.036 U56.2@78.528,14.036
USB_DCONN_N: CN15.A7 CN15.B7 U42.2 | length 6.3
  Top Layer w0.1: CN15.B7@83,6.46 v2(83,7.12) ; U42.2@83.7,10.073 83.7,9.673 83.61,9.583 83.61,8.96 v2(83.75,8.82) CN15.A7@83.75,8.16
  Bottom Layer w0.1: v2(83,7.12) 83,7.189 83.14,7.329 83.14,7.642 83.274,7.776 83.886,8.389 84.105,8.607 84.105,9.255 84.014,9.346 83.701,9.346 83.61,9.255 83.61,9.029 83.75,8.889 v2(83.75,8.82)
USB_DCONN_P: CN15.A6 CN15.B6 U42.1 | length 7.1
  Top Layer w0.1: CN15.A6@83.25,8.16 v2(83.25,8.82) 83.39,8.96 83.39,9.583 83.3,9.673 U42.1@83.3,10.073 ; CN15.B6@83.5,6.46 v2(83.5,7.12)
  Bottom Layer w0.1: v2(83.25,8.82) 83.25,8.889 83.39,9.029 83.39,9.346 83.61,9.566 84.105,9.566 84.325,9.346 84.325,8.516 83.36,7.551 83.36,7.329 83.5,7.189 v2(83.5,7.12)
USBDN1_N: U34.2 U45.6 | length 4.9
  Top Layer w0.1: U45.6@66.1,17.25 66.1,17.65 66.19,17.74 66.19,17.963 66.422,18.196 67.903,18.196 68.977,19.269 68.977,19.471 68.837,19.611 U34.2@68.837,20.006
USBDN1_P: U34.3 U45.5 | length 4.9
  Top Layer w0.1: U45.5@66.5,17.25 66.5,17.65 66.41,17.74 66.41,17.872 66.514,17.976 67.995,17.976 69.197,19.178 69.197,19.471 69.337,19.611 U34.3@69.337,20.006
USBDN2_N: U34.4 U46.6 | length 3.5
  Top Layer w0.1: U46.6@68.584,17.25 68.584,17.65 68.674,17.74 68.674,17.963 68.956,18.245 69.22,18.245 69.977,19.002 69.977,19.471 69.837,19.611 U34.4@69.837,20.006
USBDN2_P: U34.5 U46.5 | length 3.5
  Top Layer w0.1: U46.5@68.984,17.25 68.984,17.65 68.894,17.74 68.894,17.872 69.047,18.025 69.311,18.025 70.197,18.911 70.197,19.471 70.337,19.611 U34.5@70.337,20.006
USBDR_N: U1.AG22 U42.5 | length 35.1
  Top Layer w0.1: U1.AG22@66.875,34.825 66.875,34.075 66.875,33.269 67.74,32.404 67.74,30.318 68.412,29.645 70.607,29.645 74.97,25.282 74.97,16.254 77.294,13.93 82.664,13.93 83.61,12.984 83.61,11.613 83.7,11.523 U42.5@83.7,11.123
USBDR_P: U1.AF22 U42.6 | length 35.7
  Top Layer w0.09: 66.625,34.714 66.625,34.936
  Top Layer w0.1: 66.625,34.714 66.625,33.208 67.52,32.313 67.52,30.227 68.321,29.425 70.516,29.425 74.75,25.191 74.75,16.163 77.203,13.71 82.573,13.71 83.39,12.893 83.39,11.613 83.3,11.523 U42.6@83.3,11.123 ; 66.625,34.936 66.625,35.075 U1.AF22@66.875,35.325
USBH_N: U1.AG21 U34.19 | length 12.8
  Top Layer w0.1: U1.AG21@66.375,34.825 66.375,32.814 66.854,32.335 66.854,23.152 67.007,22.998 67.29,22.998 67.352,23.061 67.627,23.061 U34.19@67.705,23.138
USBH_P: U1.AF21 U34.20 | length 13.8
  Top Layer w0.1: U1.AF21@66.375,35.325 66.12,35.07 66.12,34.719 66.155,34.684 66.155,33.97 66.155,32.723 66.634,32.244 66.634,23.061 66.916,22.778 67.29,22.778 67.352,22.716 67.627,22.716 U34.20@67.705,22.638
USBSW_OE: R105.1 U1.AC17 U56.7 | length 52
  Top Layer w0.1: U1.AC17@64.375,36.825 64.379,36.829 64.379,37.346 v3(64.375,37.35) ; v1(80.421,21.305) 80.421,20.572 80.788,20.206 80.788,18.755 v1(81.278,18.265)
  Bottom Layer w0.1: v3(64.375,37.35) 64.375,36.802 63.973,36.399 63.973,35.994 64.248,35.719 64.248,34.227 64.096,34.075 62.987,32.966 62.987,32.683 62.987,24.066 61.87,22.949 61.87,16.498 63.348,15.02 71.132,15.02 77.252,21.14 79.937,21.14 80.016,21.219 80.335,21.219 v1(80.421,21.305) ; U56.7@79.268,15.776 79.268,17.15 79.854,17.736 R105.1@79.854,18.265
  Bottom Layer w0.2: R105.1@79.854,18.265 v1(81.278,18.265)
USBSW_S: R106.2 U1.AE19 U56.6 | length 43.7
  Top Layer w0.09: U1.AE19@65.375,35.825 65.675,35.525 65.675,34.075 65.675,33.925
  Top Layer w0.1: 65.675,33.925 65.675,32.244 65.649,32.218 65.649,31.294 v2(65.999,30.944) ; v1(78.472,22.81) 78.868,22.414 v1(78.868,20.495)
  Bottom Layer w0.1: v2(65.999,30.944) 65.68,30.625 65.355,30.625 64.974,30.244 64.974,29.666 64.479,29.171 64.479,24.427 62.68,22.628 62.68,19.946 63.19,19.436 66.064,19.436 66.69,18.81 71.723,18.81 75.723,22.81 v1(78.472,22.81) ; U56.6@78.868,15.776 R106.2@78.868,18.265 78.341,18.265 78.196,18.41 78.196,19.823 v1(78.868,20.495)
VBAT: C87.2 D6.3 R139.2 U1.T6 | length 77.5
  Top Layer w0.15: v3(58.875,39.933) U1.T6@58.875,40.325
  Bottom Layer w0.1: 57.719,39.325 57.974,39.426 ; 58.354,39.829 58.276,39.751 58.276,39.729 57.974,39.426 ; v3(58.875,39.933) 58.875,39.338 58.547,39.01 58.21,39.01 57.895,39.325 57.872,39.325 57.974,39.426
  Bottom Layer w0.3: 58.354,39.829 58.458,39.933 v3(58.875,39.933)
  Bottom Layer w0.4: R139.2@4.056,28.2 C87.2@4.056,29.032 4.056,29.504 4.582,30.03 D6.3@4.582,30.891 5.483,30.891 6.763,32.171 6.763,33.586 7.692,34.516 7.692,38.246 8.636,39.19 8.636,43.525 11.361,46.25 14.195,46.25 16.205,44.24 18.897,44.24 21.324,41.812 22.835,41.812 24.194,40.454 24.194,38.509 24.76,37.942 26.492,37.942 28.63,40.08 45.97,40.08 46.605,39.445 47.505,39.445 47.626,39.325 57.719,39.325
VBUS_DIV: C99.1 R219.1 R220.2 TP35.1 U1.AE5 | length 79.4
  Top Layer w0.09: 57.76,34.344 57.765,34.349 57.765,35.078 57.805,35.118 57.805,35.363 58.24,35.798 58.348,35.798 U1.AE5@58.375,35.825
  Top Layer w0.1: v2(57.271,30.982) 57.725,31.436 57.725,34.309 57.76,34.344
  Signal Layer 3 w0.1: v2(57.271,30.982) 56.921,30.632 56.921,30.011 62.256,24.676 67.127,24.676 67.625,25.175 71.636,25.175 72.486,24.325 78.319,24.325 79.459,23.185 v1(81.464,23.185)
  Bottom Layer w0.1: v1(81.464,23.185) 82.068,23.788 90.132,23.788 90.423,23.498 91.853,23.498 92.503,22.848 98.009,22.848 98.613,22.244 98.613,7.8 98.213,7.4 94.436,7.4 91.686,4.65 TP35.1@90.888,4.65
  Bottom Layer w0.15: R219.1@89.5,6.429 R220.2@89.5,5.55 89.988,5.55 TP35.1@90.888,4.65
  Bottom Layer w0.2: R219.1@89.5,6.429 C99.1@90.437,6.429
VBUS_HOST_EN: R323.2 U34.7 U41.3 | length 20
  Top Layer w0.2: U34.7@71.47,20.638 v1(71.47,20.137) R323.2@72.483,20.137
  Top Layer w0.3: U41.3@54.104,18.143 v1(55.354,18.143)
  Signal Layer 2 w0.1: v1(55.354,18.143) 56.678,19.467 65.675,19.467 66.708,20.5 68.175,20.5 68.538,20.137 v1(71.47,20.137)
VBUS_HOST_EN2: R324.2 U34.11 U41.4 | length 24.1
  Top Layer w0.15: v1(72.249,22.638) 72.477,22.867 R324.2@72.477,23.367
  Top Layer w0.2: U34.11@71.47,22.638 v1(72.249,22.638)
  Top Layer w0.3: U41.4@54.104,16.873 v1(55.354,16.873)
  Signal Layer 2 w0.1: v1(55.354,16.873) 56.958,18.477 67.652,18.477 68.6,19.425 71.875,19.425 72.674,20.224 72.674,22.213 v1(72.249,22.638)
VBUS_HOST_FAULT2n: U34.12 U41.5 | length 21.2
  Top Layer w0.2: U34.12@71.47,23.138 v1(71.47,23.64)
  Top Layer w0.3: U41.5@58.854,16.873 v1(60.104,16.873)
  Signal Layer 2 w0.1: v1(60.104,16.873) 63.926,16.873 64.443,17.39 66.914,17.39 67.199,17.675 67.775,17.675 69.025,18.925 72.125,18.925 73.225,20.025 73.225,23.015 72.6,23.64 v1(71.47,23.64)
VBUS_HOST_FAULTn: U34.8 U41.8 | length 18.1
  Top Layer w0.2: U34.8@71.47,21.138 71.942,21.138 72.154,20.926 v1(72.249,20.926)
  Top Layer w0.3: v1(57.55,20.067) 57.598,20.115 57.761,20.115 58.329,20.683 U41.8@58.854,20.683
  Signal Layer 2 w0.1: v1(57.55,20.067) 60.942,20.067 62.525,21.65 64.15,21.65 64.395,21.405 71.77,21.405 v1(72.249,20.926)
